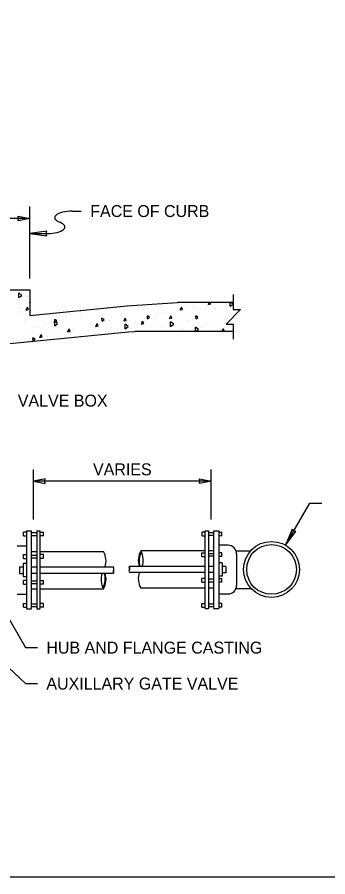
# Model space of a CAD drawing. Extents: x 99862 to 103151, y 100000 to 102076.
# Drawn here: x 102102 to 102518, y 100000 to 101148 of the extents above; entities that cross this region are included whole.
import ezdxf

# ---------------------------------------------------------------- set-up
doc = ezdxf.new("R2010")
doc.units = 0
for name, color, linetype in [('Level 1', 7, 'Continuous'), ('Level 10', 7, 'Continuous'), ('Level 14', 7, 'Continuous'), ('Level 15', 7, 'Continuous'), ('Level 17', 7, 'Continuous'), ('Level 18', 7, 'Continuous'), ('Level 20', 7, 'Continuous'), ('Level 6', 7, 'Continuous')]:
    doc.layers.add(name, color=color, linetype=linetype)

msp = doc.modelspace()

# ---------------------------------------------------------------- linework, layer by layer
at = {"layer": 'Level 1'}
msp.add_lwpolyline([(99862, 99999.5), (103151, 99999.5), (103151, 102075.5), (99862, 102075.5)], close=True, dxfattribs=at)
at = {"layer": 'Level 10'}
for p, q in [((102104.5, 100773.9), (102104.3, 100779.8)), ((102108.2, 100776.6), (102104.3, 100779.8)), ((102104.5, 100773.9), (102108.2, 100776.6)), ((102104.5, 100776.1), (102104.5, 100776.1)), ((102115.7, 100775.3), (102115.7, 100775.3)), ((102106.1, 100760.4), (102106.1, 100760.4)), ((102107.4, 100764.7), (102107.4, 100764.7)), ((102114.4, 100756.9), (102116, 100760.7)), ((102114.9, 100761.7), (102114.9, 100761.7)), ((102117.3, 100757.7), (102116, 100760.7)), ((102119.4, 100764.9), (102119.1, 100767.6)), ((102119.4, 100767.3), (102119.1, 100767.6)), ((102222.6, 100759), (102222.6, 100759)), ((102234, 100759), (102234, 100759)), ((102247.1, 100762), (102247.1, 100762)), ((102276.1, 100759), (102276.1, 100759)), ((102320.2, 100757.2), (102322.1, 100760.7)), ((102320.5, 100763.6), (102320.5, 100763.6)), ((102323.4, 100757.7), (102322.1, 100760.7)), ((102326.9, 100762), (102326.9, 100762)), ((102333.5, 100766.5), (102333.5, 100766.5)), ((102338, 100761.2), (102338, 100761.2)), ((102355.3, 100762), (102355.3, 100762)), ((102358, 100764.3), (102359.1, 100767.1)), ((102358, 100764.3), (102361.2, 100765.2)), ((102361.2, 100765.2), (102360.1, 100767.1)), ((102367.6, 100760.9), (102367.6, 100760.9)), ((102382.7, 100763.3), (102382.7, 100763.3)), ((102387.2, 100762), (102387, 100767.1)), ((102387.2, 100762), (102391, 100764.9)), ((102391, 100764.9), (102388.1, 100767.1)), ((102103.7, 100751.1), (102103.7, 100751.1)), ((102114.4, 100756.9), (102117.3, 100757.7)), ((102118.4, 100747.3), (102118.4, 100747.3)), ((102170.2, 100754), (102170.2, 100754)), ((102187.5, 100754.8), (102187.5, 100754.8)), ((102187.8, 100752.2), (102187.8, 100752.2)), ((102214.4, 100748.4), (102214.4, 100748.4)), ((102215.2, 100755.8), (102215.2, 100755.8)), ((102228.5, 100748.2), (102228.5, 100748.2)), ((102239.9, 100750.5), (102239.9, 100750.5)), ((102275.3, 100751.6), (102275.3, 100751.6)), ((102276.6, 100745.2), (102276.3, 100749.2)), ((102279.3, 100747.3), (102276.3, 100749.2)), ((102289.3, 100751.3), (102289.3, 100751.3)), ((102300.8, 100753.7), (102300.8, 100753.7)), ((102306.1, 100745.8), (102307.7, 100749.4)), ((102309, 100746.2), (102307.7, 100749.4)), ((102320.2, 100757.2), (102323.4, 100757.7)), ((102338.9, 100749), (102338.9, 100749)), ((102341.5, 100745.2), (102341.2, 100749.2)), ((102343.9, 100747.1), (102341.2, 100749.2)), ((102342, 100758.8), (102342, 100758.8)), ((102352.9, 100756.1), (102352.9, 100756.1)), ((102367.6, 100757.5), (102367.6, 100757.5)), ((102385.9, 100749), (102385.9, 100749)), ((102112.3, 100739.9), (102112.3, 100739.9)), ((102137.8, 100742), (102137.8, 100742)), ((102139.9, 100738), (102139.9, 100738)), ((102152.4, 100735.9), (102152.1, 100742)), ((102156.1, 100738.8), (102152.1, 100742)), ((102152.4, 100735.9), (102156.1, 100738.8)), ((102152.9, 100740.5), (102152.7, 100744.4)), ((102155.3, 100742.6), (102152.7, 100744.4)), ((102152.9, 100740.5), (102155.3, 100742.6)), ((102159.1, 100742.8), (102159.1, 100742.8)), ((102163.3, 100744.2), (102163.3, 100744.2)), ((102180.3, 100747.1), (102180.3, 100747.1)), ((102188.8, 100746.3), (102188.8, 100746.3)), ((102199.7, 100739.1), (102199.7, 100739.1)), ((102207.4, 100735.1), (102209.1, 100738.8)), ((102207.4, 100735.1), (102210.6, 100735.9)), ((102210.6, 100735.9), (102209.1, 100738.8)), ((102213.3, 100739.9), (102213.3, 100739.9)), ((102215.7, 100742), (102215.5, 100746)), ((102218.4, 100744.2), (102215.5, 100746)), ((102215.7, 100742), (102218.4, 100744.2)), ((102226.1, 100742.6), (102226.1, 100742.6)), ((102245.2, 100742.6), (102246.8, 100746.3)), ((102245.2, 100742.6), (102248.1, 100743.1)), ((102246.5, 100731.9), (102246.5, 100738)), ((102250.6, 100734.9), (102246.5, 100738)), ((102248.1, 100743.1), (102246.8, 100746.3)), ((102260.6, 100742.3), (102260.6, 100742.3)), ((102268.3, 100738.3), (102269.9, 100742)), ((102268.3, 100738.3), (102271.5, 100739.1)), ((102271.5, 100739.1), (102269.9, 100742)), ((102274.2, 100743), (102274.2, 100743)), ((102276.6, 100745.2), (102279.3, 100747.3)), ((102287, 100745.8), (102287, 100745.8)), ((102288.5, 100737.5), (102288.5, 100737.5)), ((102301.6, 100738.3), (102301.6, 100738.3)), ((102306.1, 100745.8), (102309, 100746.2)), ((102307.4, 100735.1), (102307.4, 100741.2)), ((102311.5, 100738), (102307.4, 100741.2)), ((102307.4, 100735.1), (102311.5, 100738)), ((102314.1, 100735.9), (102314.1, 100735.9)), ((102329.8, 100742.6), (102329.8, 100742.6)), ((102332.2, 100737), (102332.2, 100737)), ((102337, 100736.2), (102337, 100736.2)), ((102341.5, 100745.2), (102343.9, 100747.1)), ((102350.8, 100735.9), (102350.8, 100735.9)), ((102364.6, 100737.5), (102364.6, 100737.5)), ((102372.6, 100736.2), (102372.6, 100736.2)), ((102379.5, 100744.4), (102379.5, 100744.4)), ((102380.9, 100746.8), (102380.9, 100746.8)), ((102113.1, 100726.6), (102113.1, 100726.6)), ((102125.5, 100725.8), (102125.5, 100725.8)), ((102126.9, 100735.4), (102126.9, 100735.4)), ((102130.4, 100734.3), (102130.4, 100734.3)), ((102152.1, 100728.2), (102152.1, 100728.2)), ((102159.3, 100727.9), (102159.3, 100727.9)), ((102169.4, 100729), (102169.4, 100729)), ((102169.9, 100727.9), (102171.5, 100731.7)), ((102169.9, 100727.9), (102173.2, 100728.5)), ((102171, 100729.8), (102171, 100729.8)), ((102173.2, 100728.5), (102171.5, 100731.7)), ((102176.6, 100730.1), (102176.6, 100730.1)), ((102196.8, 100730.1), (102196.8, 100730.1)), ((102212, 100726.1), (102212, 100726.1)), ((102227.7, 100734.3), (102227.7, 100734.3)), ((102235.9, 100731.9), (102235.9, 100731.9)), ((102240.7, 100735.1), (102240.7, 100735.1)), ((102245.7, 100732.5), (102245.7, 100732.5)), ((102246.5, 100731.9), (102250.6, 100734.9)), ((102253.2, 100732.7), (102253.2, 100732.7)), ((102296.8, 100735.1), (102296.8, 100735.1)), ((102306.6, 100735.6), (102306.6, 100735.6)), ((102319.7, 100735.6), (102319.7, 100735.6)), ((102321.6, 100731.9), (102321.6, 100731.9)), ((102340.7, 100728.2), (102340.7, 100734.1)), ((102344.7, 100730.9), (102340.7, 100734.1)), ((102340.7, 100728.2), (102344.7, 100730.9)), ((102347.1, 100734.1), (102347.1, 100734.1)), ((102364.9, 100729.8), (102364.9, 100729.8)), ((102376.1, 100728.2), (102377.7, 100731.7)), ((102376.6, 100728.2), (102379.3, 100728.8)), ((102379.3, 100728.8), (102377.7, 100731.7)), ((102377.9, 100732.5), (102377.9, 100732.5)), ((102105.9, 100716), (102105.9, 100716)), ((102117.3, 100715.2), (102117.3, 100715.2)), ((102118.9, 100718.9), (102118.9, 100718.9)), ((102123.7, 100716), (102123.1, 100720)), ((102126.1, 100717.8), (102123.1, 100720)), ((102123.7, 100716), (102126.1, 100718.1)), ((102132.5, 100720.5), (102134.1, 100724.2)), ((102132.5, 100720.5), (102135.4, 100721.3)), ((102135.4, 100721.3), (102134.1, 100724.2)), ((102142.3, 100721.3), (102142.3, 100721.3)), ((102142.8, 100717.3), (102142.8, 100717.3)), ((102168.4, 100719.4), (102168.4, 100719.4)), ((102186.2, 100720.7), (102186.2, 100721.5)), ((102187, 100721), (102186.2, 100721.5)), ((102205.3, 100723.4), (102205.3, 100723.4))]:
    msp.add_line(p, q, dxfattribs=at)
at = {"layer": 'Level 14'}
for p, q in [((102175.9, 100889.3), (102187.9, 100889.3)), ((102119.1, 100859.3), (102142.6, 100859.3))]:
    msp.add_line(p, q, dxfattribs=at)
msp.add_lwpolyline([(102119.1, 100859.3), (102142, 100856.3), (102140.9, 100859.3), (102142, 100862.3)], close=True, dxfattribs=at)
for centre, start_param, end_param in [((102175.7, 100880.5), 4.705244, 7.068624), ((102142.6, 100868.1), 1.570796, 3.926959)]:
    msp.add_ellipse(centre, major_axis=(-23.4, 0), ratio=0.375, start_param=start_param, end_param=end_param, dxfattribs=at)
at = {"layer": 'Level 15'}
for p, q in [((102119.1, 100799.1), (102119.1, 100895.3)), ((102119.1, 100879.3), (101855.6, 100879.3)), ((102124.1, 100476.9), (102124.1, 100544)), ((102361.7, 100476.9), (102361.7, 100544)), ((102361.7, 100528.1), (102124.1, 100528.1)), ((102461.1, 100442.7), (102493.6, 100499)), ((102493.6, 100499), (102509.6, 100499)), ((102067.6, 100384.8), (102113.2, 100305.8)), ((102113.2, 100305.8), (102129.2, 100305.8)), ((102113.2, 100257.8), (102129.2, 100257.8))]:
    msp.add_line(p, q, dxfattribs=at)
for points in [[(102119.1, 100879.3), (102103.4, 100876.2), (102104.1, 100879.3), (102103.4, 100882.4)], [(102124.1, 100528.1), (102139.8, 100525), (102139, 100528.1), (102139.8, 100531.2)], [(102361.7, 100528.1), (102346, 100525), (102346.7, 100528.1), (102346, 100531.2)], [(102461.1, 100442.7), (102475.1, 100461), (102472, 100461.6), (102470, 100464)]]:
    msp.add_lwpolyline(points, close=True, dxfattribs=at)
msp.add_lwpolyline([(102391.2, 100777.6), (102391.2, 100757.6), (102400.9, 100757.6), (102381.5, 100738.2), (102391.2, 100738.2), (102391.2, 100718.2)], dxfattribs=at)
at = {"layer": 'Level 17'}
for p, q in [((102248.9, 100762.8), (102316.8, 100767.3)), ((102391.8, 100767.3), (102316.8, 100767.3)), ((102391.2, 100728.2), (102259.6, 100728.2))]:
    msp.add_line(p, q, dxfattribs=at)
msp.add_lwpolyline([(102259.6, 100727.9), (102251, 100727.4), (102087.8, 100711.2), (102087.8, 100784.1), (102119.1, 100784.1), (102119.1, 100749.5), (102248.9, 100762.8), (102249.2, 100762.8)], dxfattribs=at)
at = {"layer": 'Level 18'}
for p, q in [((102114.8, 100461.9), (102114.8, 100357.8)), ((102114.8, 100461.9), (102121.2, 100461.9)), ((102121.2, 100357.9), (102121.2, 100461.9)), ((102128.6, 100461.9), (102128.6, 100357.9)), ((102128.6, 100461.9), (102133.1, 100461.9)), ((102133.1, 100357.9), (102133.1, 100461.9)), ((102353.4, 100460.2), (102349.4, 100460.2)), ((102349.4, 100455.2), (102349.4, 100460.2)), ((102353.4, 100357.9), (102353.4, 100461.9)), ((102353.4, 100461.9), (102357.9, 100461.9)), ((102357.9, 100461.9), (102357.9, 100357.9)), ((102365.4, 100357.9), (102365.4, 100461.9)), ((102365.4, 100461.9), (102371.7, 100461.9)), ((102371.7, 100461.9), (102371.7, 100357.9)), ((102371.7, 100460.2), (102375.8, 100460.2)), ((102375.8, 100455.2), (102375.8, 100460.2)), ((102110.7, 100455.1), (102110.7, 100460.1)), ((102114.8, 100460.1), (102110.7, 100460.1)), ((102110.7, 100455.1), (102114.8, 100455.1)), ((102128.6, 100459.3), (102121.2, 100459.3)), ((102121.2, 100455.8), (102128.6, 100455.8)), ((102133.3, 100460.1), (102137.4, 100460.1)), ((102137.4, 100455.1), (102133.3, 100455.1)), ((102137.4, 100455.1), (102137.4, 100460.1)), ((102349.4, 100455.2), (102353.4, 100455.2)), ((102365.4, 100459.4), (102357.9, 100459.4)), ((102357.9, 100455.9), (102365.4, 100455.9)), ((102375.8, 100455.2), (102371.7, 100455.2)), ((102110.7, 100425.1), (102110.7, 100430.1)), ((102110.7, 100430.1), (102114.8, 100430.1)), ((102121.2, 100429.3), (102128.6, 100429.3)), ((102121.2, 100425.9), (102128.6, 100425.9)), ((102137.4, 100430.1), (102133.3, 100430.1)), ((102137.4, 100425.1), (102137.4, 100430.1)), ((102349.3, 100432.5), (102353.4, 100432.5)), ((102349.3, 100427.5), (102349.3, 100432.5)), ((102349.3, 100427.5), (102353.4, 100427.5)), ((102357.9, 100431.7), (102365.4, 100431.7)), ((102357.9, 100428.3), (102365.4, 100428.3)), ((102375.7, 100432.5), (102371.7, 100432.5)), ((102375.7, 100427.5), (102371.7, 100427.5)), ((102375.7, 100427.5), (102375.7, 100432.5)), ((102110.3, 100418.6), (102110.3, 100400.7)), ((102110.3, 100418.6), (102114.8, 100418.6)), ((102110.7, 100425.1), (102114.8, 100425.1)), ((102137.4, 100425.1), (102133.3, 100425.1)), ((102353.4, 100414.2), (102252.2, 100414.2)), ((102365.4, 100414.2), (102357.9, 100414.2)), ((102376.2, 100419.3), (102371.7, 100419.3)), ((102376.2, 100419.3), (102376.2, 100401.3)), ((102381.2, 100414.2), (102376.2, 100414.2)), ((102105.3, 100413.6), (102110.3, 100413.6)), ((102105.3, 100413.4), (102105.3, 100405.1)), ((102105.3, 100405.1), (102110.3, 100405.1)), ((102121.2, 100413.6), (102128.6, 100413.6)), ((102121.2, 100405.4), (102128.6, 100405.4)), ((102133.1, 100413.6), (102230.9, 100413.6)), ((102133.1, 100405.4), (102230.9, 100405.4)), ((102353.4, 100406), (102252.2, 100406)), ((102365.4, 100406), (102357.9, 100406)), ((102381.2, 100405.8), (102376.2, 100405.8)), ((102381.2, 100414), (102381.2, 100405.8)), ((102110.3, 100400.7), (102114.8, 100400.7)), ((102110.7, 100390.6), (102110.7, 100395.5)), ((102114.8, 100395.5), (102110.7, 100395.5)), ((102128.6, 100394.8), (102121.2, 100394.8)), ((102121.2, 100391.3), (102128.6, 100391.3)), ((102133.1, 100395.5), (102137.4, 100395.5)), ((102137.4, 100390.6), (102137.4, 100395.5)), ((102353.4, 100398.1), (102349.3, 100398.1)), ((102349.3, 100393.1), (102349.3, 100398.1)), ((102349.3, 100393.1), (102353.4, 100393.1)), ((102365.4, 100397.4), (102357.9, 100397.4)), ((102357.9, 100393.9), (102365.4, 100393.9)), ((102376.2, 100401.3), (102371.7, 100401.3)), ((102371.7, 100398.1), (102375.7, 100398.1)), ((102375.7, 100393.1), (102371.7, 100393.1)), ((102375.7, 100393.1), (102375.7, 100398.1)), ((102110.7, 100390.6), (102114.8, 100390.6)), ((102137.4, 100390.6), (102133.1, 100390.6)), ((102110.7, 100360.1), (102110.7, 100365)), ((102110.7, 100365), (102114.8, 100365)), ((102110.7, 100360.1), (102114.8, 100360.1)), ((102114.8, 100357.8), (102121.2, 100357.8)), ((102121.2, 100364.3), (102128.6, 100364.3)), ((102121.2, 100360.8), (102128.6, 100360.8)), ((102128.6, 100357.8), (102133.1, 100357.8)), ((102137.4, 100365), (102133.1, 100365)), ((102137.4, 100360.1), (102133.1, 100360.1)), ((102137.4, 100360.1), (102137.4, 100365)), ((102349.3, 100365), (102353.4, 100365)), ((102349.3, 100360), (102349.3, 100365)), ((102349.3, 100360), (102353.4, 100360)), ((102353.4, 100357.9), (102357.9, 100357.9)), ((102357.9, 100364.3), (102365.4, 100364.3)), ((102357.9, 100360.8), (102365.4, 100360.8)), ((102365.4, 100357.9), (102371.7, 100357.9)), ((102375.7, 100365), (102371.7, 100365)), ((102375.7, 100360), (102371.7, 100360)), ((102375.7, 100360), (102375.7, 100365))]:
    msp.add_line(p, q, dxfattribs=at)
for centre, start, end in [((102255.8, 100412.2), 150, 210), ((102248.7, 100412.2), 330, 30), ((102234.5, 100407.4), 150, 210), ((102227.3, 100411.5), 330, 30), ((102227.3, 100407.4), 330, 30), ((102255.8, 100408.1), 150, 210)]:
    msp.add_arc(centre, 4.11, start, end, dxfattribs=at)
at = {"layer": 'Level 20'}
msp.add_line((101999.7, 100364.7), (102113.2, 100257.8), dxfattribs=at)
at = {"layer": 'Level 6'}
for p, q in [((102102.2, 100442), (102114.8, 100442)), ((102384.4, 100442.7), (102371.7, 100442.7)), ((102121.2, 100434.3), (102128.6, 100434.3)), ((102133.1, 100434.3), (102217.6, 100434.3)), ((102353.4, 100435), (102267.5, 100435)), ((102365.4, 100435), (102357.9, 100435)), ((102395.1, 100435), (102414.4, 100435)), ((102395.7, 100431.3), (102395.7, 100388.9)), ((102121.2, 100384.6), (102128.6, 100384.6)), ((102133.1, 100384.6), (102217.6, 100384.6)), ((102353.4, 100385.2), (102267.5, 100385.2)), ((102365.4, 100385.2), (102357.9, 100385.2)), ((102395, 100384.8), (102415.2, 100384.8)), ((102114.8, 100376.9), (102102.2, 100376.9)), ((102371.7, 100377.5), (102384.4, 100377.5))]:
    msp.add_line(p, q, dxfattribs=at)
for radius in [37.4, 33.2]:
    msp.add_circle((102442.4, 100410.3), radius, dxfattribs=at)
for centre, radius, start, end in [((102384.4, 100431.3), 11.3, 0, 90), ((102196.1, 100421.8), 24.9, 340.5797, 30), ((102289.1, 100422.5), 24.9, 150, 199.4814), ((102292, 100421.2), 26.8, 152.351, 195.0063), ((102246, 100422.5), 24.9, 340.5186, 30), ((102239.2, 100397), 24.9, 160.488, 210), ((102193.1, 100398.4), 26.9, 332.3476, 15.0573), ((102196.1, 100397), 24.9, 330, 19.6649), ((102289.1, 100397.6), 24.9, 160.3351, 210), ((102384.4, 100388.9), 11.3, 270, 0)]:
    msp.add_arc(centre, radius, start, end, dxfattribs=at)

# ---------------------------------------------------------------- texts
at = {"layer": 'Level 20'}
for s, p in [('FACE OF CURB', (102199.9, 100881.3)), ('VALVE BOX', (102103, 100627.9)), ('VARIES', (102203.6, 100536.1)), ('HUB AND FLANGE CASTING', (102141.2, 100297.8)), ('AUXILLARY GATE VALVE', (102141.2, 100249.8))]:
    msp.add_text(s, height=16, dxfattribs=at).set_placement(p)

doc.saveas('drawing.dxf')
